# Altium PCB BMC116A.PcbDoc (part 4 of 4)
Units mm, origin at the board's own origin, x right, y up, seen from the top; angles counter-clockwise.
Board outline 154.94 x 104.14 mm, 6 copper layers (Top Layer, Signal Layer 1, Signal Layer 2, Signal Layer 3, Signal Layer 4, Bottom Layer), stack 1.56 mm thick; 252 components, 114 nets, 652 pads, 2530 vias.
Unrouted connection lines stored in the file: 13.
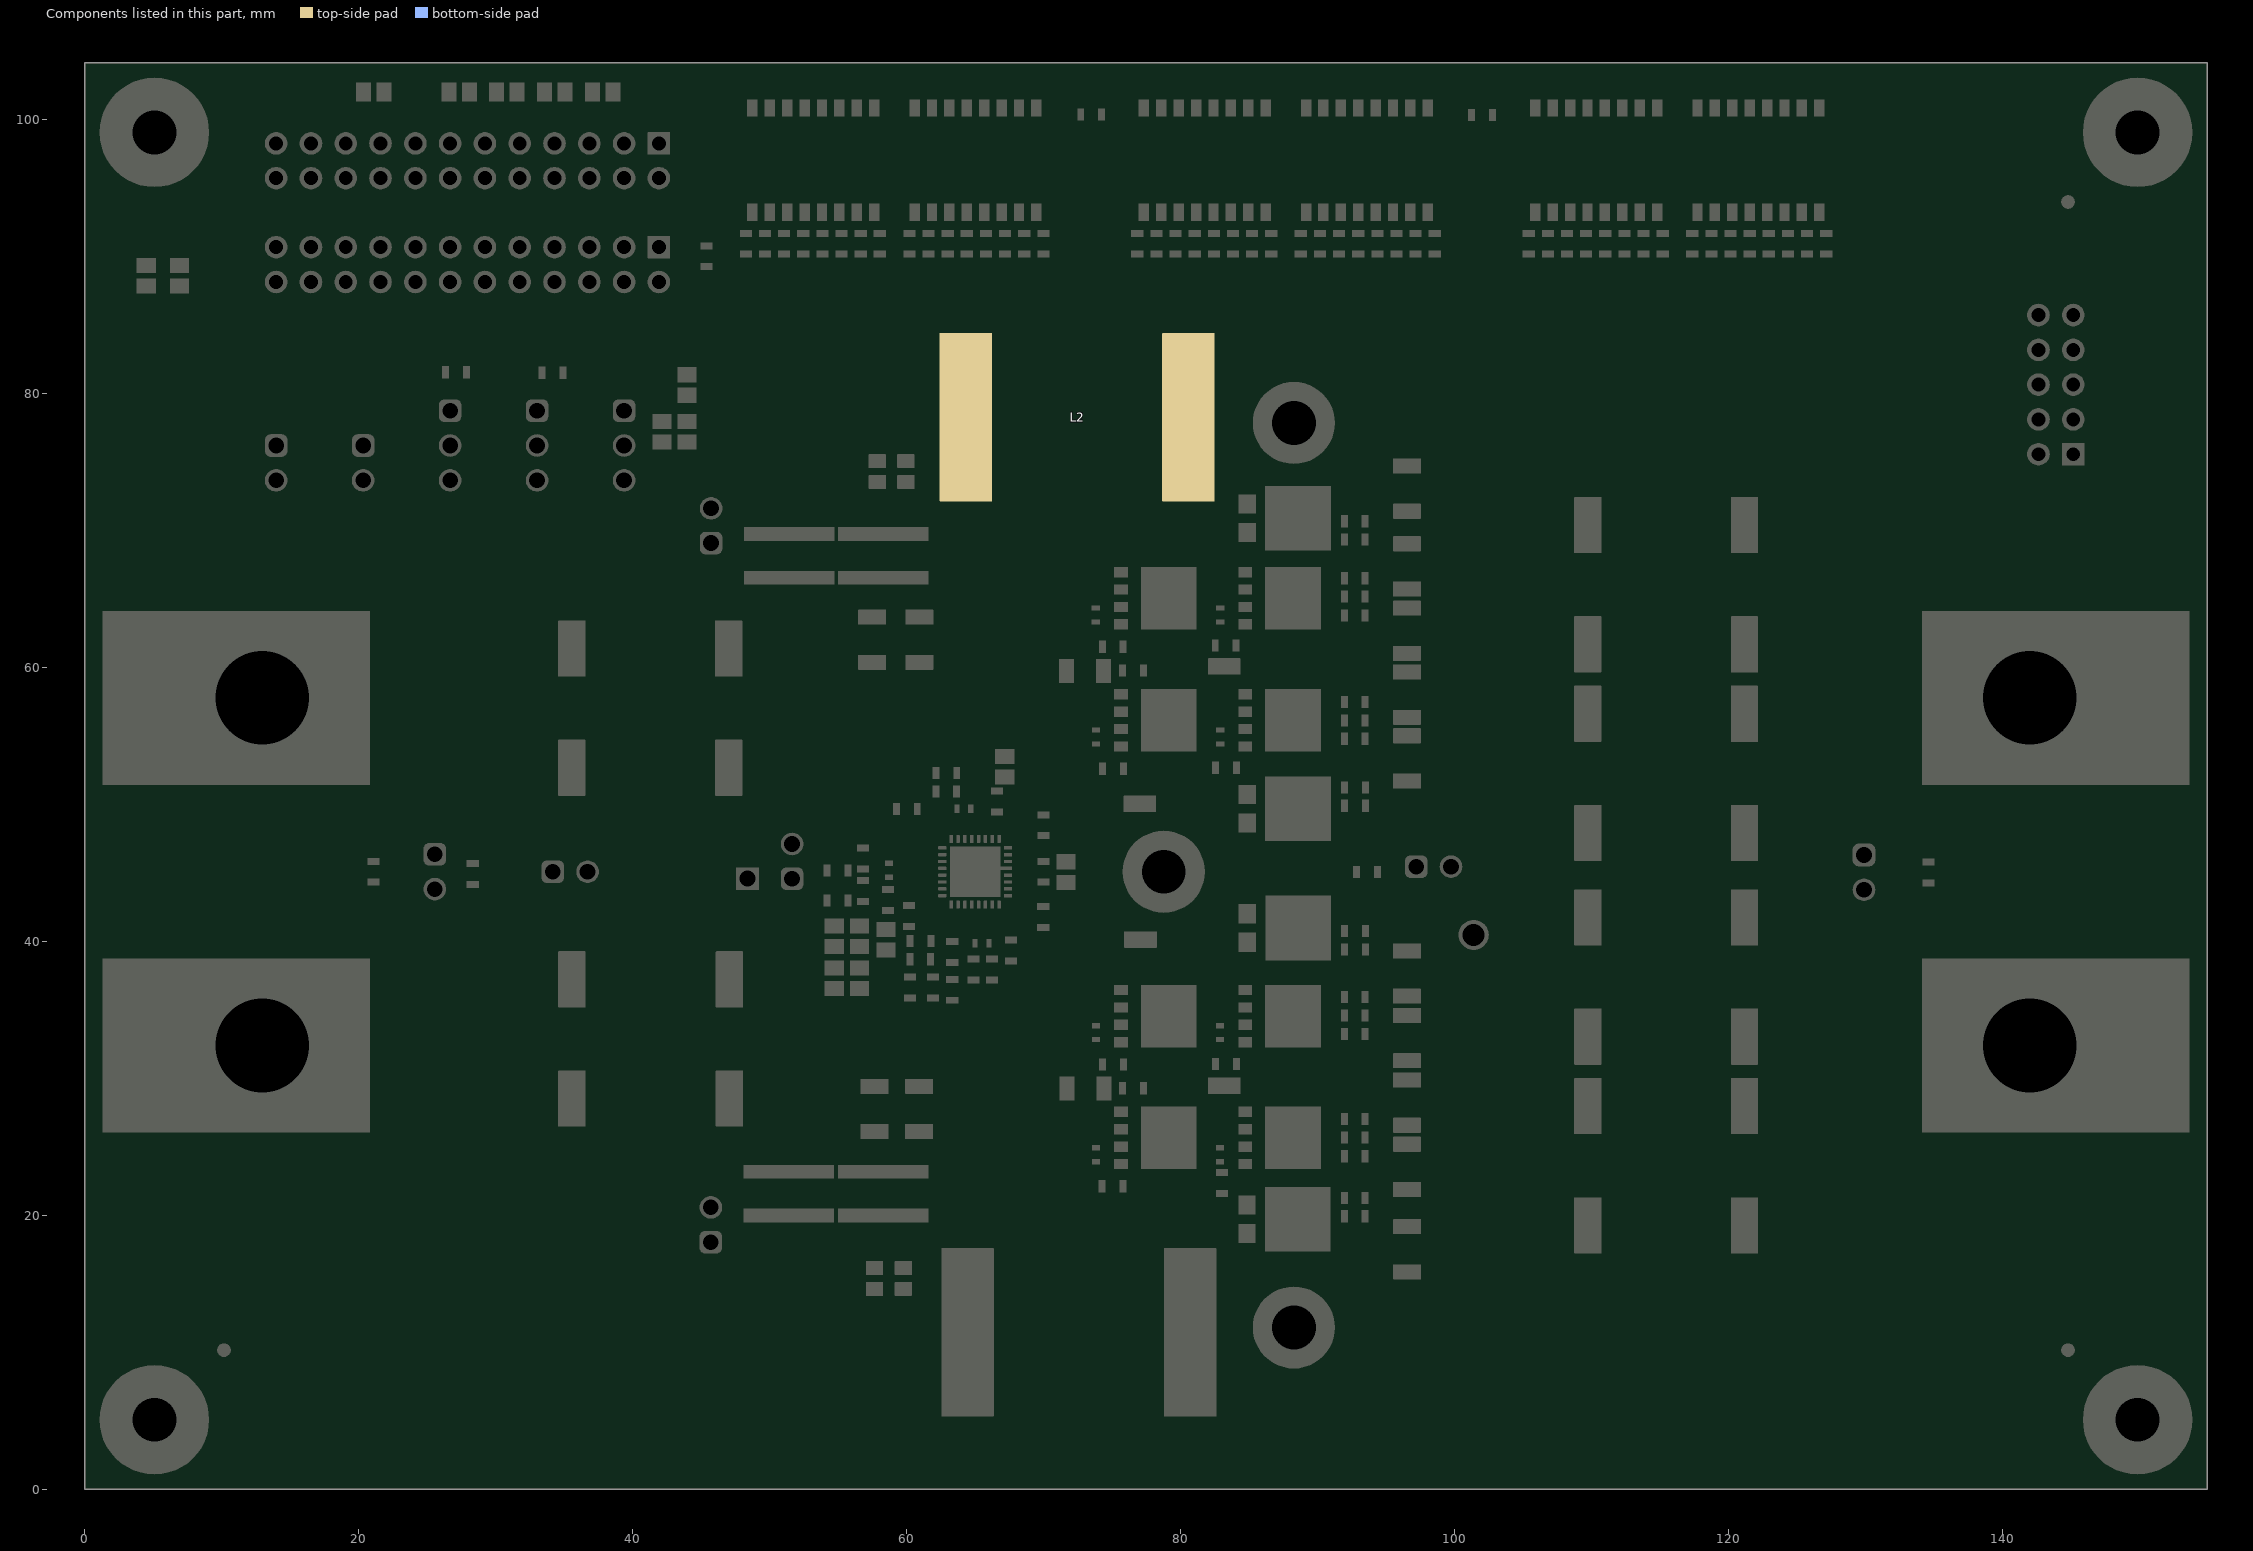
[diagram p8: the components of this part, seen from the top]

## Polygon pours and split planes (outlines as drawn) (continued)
AGND on Top Layer "TOP_LAYER_AGND_P106" (solid, pour order 106): 54.666,51.983 50.361,47.677 50.361,38.929 54.382,34.907 66.117,34.907 68.147,36.938 68.147,40.746 67.196,41.697 67.196,47.527 67.846,48.177 67.846,54.07 66.872,55.045 57.729,55.045
VIN on Top Layer "TOP_LAYER_VIN_P107" (solid, pour order 107): 30.48,22.595 31.197,21.878 61.963,21.878 61.963,27.444 61.54,27.867 62.851,27.924 50.892,27.919 47.741,31.07 31.197,31.07 30.48,30.353
VIN on Top Layer "TOP_LAYER_VIN_P108" (solid, pour order 108): 30.503,59.468 30.503,67.206 31.149,67.852 61.987,67.852 61.987,62.079 61.727,61.819 50.721,61.807 47.715,58.801 31.17,58.801
SW2 on Top Layer "TOP_LAYER_SW2_P109" (solid, pour order 109): 85.528,47.938 85.394,47.804 82.005,47.804 77.02,52.789 77.02,72.111 74.704,74.949 74.704,80.783 78.416,84.494 82.989,84.494 83.386,84.098 83.386,74.558 84.623,73.356 85.528,73.356 85.528,68.383
VOUT on Top Layer "Bottom Layer-VOUT" (solid, pour order 110): 130.5,45.095 129.307,44.926 128.679,44.648 126.251,42.219 124.968,38.73 124.968,27.161 122.353,23.823 118.788,22.225 105.001,22.225 100.063,17.287 86.106,17.286 86.117,44.196 86.117,46.568 86.106,46.568 86.106,73.356 99.971,73.356 101.243,72.084 106.017,67.31 118.237,67.31 154.94,67.31 154.94,45.095
VIN on Top Layer "TOP_LAYER_VIN_P130" (solid, remove dead copper, pour order 130): 23.497,66.112 23.497,49.085 22.859,48.448 0,48.448 0,66.733 22.876,66.733
GND on Top Layer "TOP_LAYER_AGND_P479" (solid, pour order 131): -0.666,104.208 154.274,104.208 154.274,0.068 -0.666,0.068
GND on Top Layer "TOP_LAYER_GND_P132" (solid, pour order 132): 92.892,32.786 93.052,32.626 97.51,32.626 97.962,33.078 97.962,35.656 97.092,36.525 93.088,36.525 92.892,36.329
GND on Top Layer "TOP_LAYER_GND_P008" (solid, pour order 8): 92.892,54.306 93.065,54.132 97.79,54.132 97.962,54.304 97.962,57.12 97.037,58.045 93.088,58.045 92.892,57.848
GND on Bottom Layer "BOTTOM_LAYER_GND_P066" (solid, pour order 66): 56.96,30.206 56.96,28.69 57.166,28.484 62.038,28.484 62.313,28.759 62.313,30.041 61.966,30.387 57.185,30.387
GND on Bottom Layer "BOTTOM_LAYER_GND_P081" (solid, pour order 81): 57.017,59.556 57.017,61.072 57.223,61.278 62.095,61.278 62.37,61.003 62.37,59.721 62.024,59.375 57.243,59.375
VOUT on Bottom Layer "Bottom Layer-VOUT 1" (solid, pour order 117): 86.454,47.602 86.646,47.41 90.399,47.41 90.599,47.611 90.599,58.906 90.417,59.089 86.633,59.089 86.454,58.866
VOUT on Bottom Layer "Bottom Layer-VOUT 2" (solid, pour order 116): 86.445,31.796 86.61,31.631 90.42,31.631 90.611,31.823 90.611,43.062 90.409,43.265 86.656,43.265 86.445,43.054
VOUT on Bottom Layer "Bottom Layer-VOUT 3" (solid, pour order 112): 90.402,17.469 90.573,17.681 90.573,28.453 90.417,28.609 86.633,28.609 86.445,28.376 86.445,17.653 86.63,17.469
VOUT on Bottom Layer "Bottom Layer-VOUT 4" (solid, pour order 91): 86.471,62.25 86.61,62.111 90.42,62.111 90.573,62.264 90.573,72.991 90.395,73.17 86.642,73.17 86.471,72.999
SW2 on Bottom Layer "BOTTOM_LAYER_SW2_P121" (solid, remove dead copper, pour order 121): 77.304,68.646 81.087,68.646 81.241,68.492 81.241,61.622 81.06,61.441 77.305,61.441 77.124,61.622 77.124,68.423
SW2 on Bottom Layer "BOTTOM_LAYER_SW2_P120" (solid, pour order 120): 77.303,59.748 81.086,59.748 81.24,59.594 81.24,52.723 81.059,52.543 77.304,52.543 77.124,52.723 77.124,59.525
SW1 on Bottom Layer "BOTTOM_LAYER_SW1_P119" (solid, pour order 119): 77.303,29.268 81.086,29.268 81.24,29.114 81.24,22.244 81.059,22.063 77.304,22.063 77.124,22.243 77.124,29.045
SW1 on Bottom Layer "BOTTOM_LAYER_SW1_P118" (solid, pour order 118): 77.304,38.166 81.087,38.166 81.241,38.012 81.241,31.142 81.06,30.961 77.305,30.961 77.124,31.142 77.124,37.943
AGND on Bottom Layer "Bottom Layer-AGND" (solid, remove dead copper, pour order 126): 35.434,44.314 49.332,30.314 49.332,24.198 63.06,24.198 68.022,29.16 68.022,40.637 67.317,41.343 66.51,41.343 65.75,42.103 65.75,43.248 66.86,44.358 66.86,45.788 65.696,46.952 65.696,47.871 68.022,50.197 68.089,76.912 49.332,95.669 49.332,95.668 41.482,103.518 0.647,103.518 0.647,68.286 41.934,68.314 44.32,65.928 49.332,65.928 49.332,59.666 35.434,45.768
GND on Bottom Layer "BOTTOM_LAYER_GND_P125" (solid, remove dead copper, pour order 125): 59.866,61.287 62.023,61.287 62.37,60.939 62.37,59.721 62.032,59.383 59.863,59.383 59.532,59.714 59.532,60.953
GND on Bottom Layer "BOTTOM_LAYER_GND_P124" (solid, remove dead copper, pour order 124): 57.225,61.287 58.721,61.287 59.068,60.939 59.068,59.721 58.73,59.383 57.203,59.383 57.017,59.569 57.017,61.079
GND on Bottom Layer "BOTTOM_LAYER_GND_P123" (solid, remove dead copper, pour order 123): 57.2,28.459 58.695,28.459 59.043,28.806 59.043,30.024 58.704,30.363 57.178,30.363 56.992,30.177 56.992,28.666
GND on Bottom Layer "BOTTOM_LAYER_GND_P122" (solid, remove dead copper, pour order 122): 59.808,28.475 61.965,28.475 62.313,28.823 62.313,30.041 61.974,30.379 59.805,30.379 59.474,30.048 59.474,28.809
VOUT on Bottom Layer "BOTTOM_LAYER_VOUT_P127" (solid, remove dead copper, pour order 127): 131.217,49.293 131.217,66.32 131.935,67.038 154.94,67.038 154.94,48.673 131.838,48.673
GND on Bottom Layer "BOTTOM_LAYER_GND_P128" (solid, remove dead copper, pour order 128): 23.723,40.877 23.723,23.85 23.005,23.132 0,23.132 0,41.497 23.102,41.497
VIN on Bottom Layer "Bottom Layer-VIN" (solid, remove dead copper, pour order 129): 48.768,24.211 44.01,24.211 41.588,21.789 0,21.789 0,67.775 41.828,67.775 44.017,65.586 48.768,65.586
GND on Bottom Layer "TOP_LAYER_AGND_P479" (solid, pour order 134): 0,104.14 154.94,104.14 154.94,0 0,0
VOUT on Bottom Layer "BOTTOM_LAYER_VOUT_P133" (solid, remove dead copper, pour order 133): 131.217,49.293 131.217,66.32 131.855,66.958 154.94,66.958 154.94,48.673 131.838,48.673
GND on Signal Layer 2 "Signal Layer 2-GND" (solid, remove dead copper, pour order 29): 74.439,21.512 75.252,22.324 75.252,66.938 74.371,67.818 69.175,67.818 68.58,67.223 68.58,50.014 66.336,47.77 66.336,46.991 67.337,45.99 67.34,44.083 66.287,43.029 66.287,42.241 66.776,41.752 67.613,41.752 68.58,40.785 68.58,21.917 68.986,21.512
AGND on Signal Layer 2 "TOP_LAYER_AGND_P479" (solid, pour order 51): 0,104.14 154.94,104.14 154.94,0 0,0
GND on Signal Layer 3 "Signal Layer 3-GND" (solid, remove dead copper, pour order 70): 85.695,28.878 85.695,31.323 85.695,59.358 85.695,61.803 85.695,65.588 82.65,68.632 70.04,68.632 68.58,67.172 68.58,50.014 66.336,47.77 66.336,47.005 67.345,45.996 67.348,44.103 66.287,43.041 66.287,42.257 66.8,41.743 67.585,41.743 68.58,40.748 68.58,21.928 69.004,21.503 83.796,21.503 85.695,23.402
AGND on Signal Layer 3 "TOP_LAYER_AGND_P479" (solid, pour order 72): 0,104.14 154.94,104.14 154.94,0 0,0
GND on Signal Layer 4 "Signal Layer 4-GND" (solid, remove dead copper, pour order 47): 85.695,23.402 85.695,65.588 82.651,68.631 70.039,68.631 68.58,67.172 68.58,49.982 66.26,47.662 66.26,47.134 67.356,46.038 67.359,44.114 66.287,43.041 66.287,42.257 66.797,41.747 67.489,41.747 68.58,40.656 68.58,21.928 69.426,21.082 83.375,21.082
AGND on Signal Layer 4 "TOP_LAYER_AGND_P479" (solid, pour order 50): 0,104.14 154.94,104.14 154.94,0 0,0
no net on Top Solder "TOP_LAYER_NONET_P111" (solid): 71.602,10.338 70.408,10.338 70.408,13.696 71.602,13.696
no net on Top Solder "TOP_LAYER_NONET_P111" (solid): 71.472,79.391 70.278,79.391 70.278,76.033 71.472,76.033
no net on Top Solder "TOP_LAYER_NONET_P111" (solid): 70.179,8.919 66.639,8.919 66.639,14.765 70.179,14.765
no net on Top Solder "TOP_LAYER_NONET_P111" (solid): 74.96,8.919 78.5,8.919 78.5,14.765 74.96,14.765
no net on Top Solder "TOP_LAYER_NONET_P111" (solid): 74.83,80.81 78.37,80.81 78.37,74.964 74.83,74.964
L2 on Top Solder "TOP_LAYER_NONET_P111" (solid, pour order 111): 70.049,80.81 66.51,80.81 66.51,74.964 70.049,74.964
GND on Signal Layer 1 "TOP_LAYER_AGND_P479" (solid, pour order 25): 0,104.14 154.94,104.14 154.94,0 0,0
VOUT on Bottom Solder (solid, pour order 32): 86.471,62.25 86.61,62.111 90.42,62.111 90.573,62.264 90.573,72.991 90.395,73.17 86.642,73.17 86.471,72.999
VOUT on Bottom Solder (solid, pour order 33): 90.402,17.469 90.573,17.681 90.573,28.453 90.417,28.609 86.633,28.609 86.445,28.376 86.445,17.653 86.63,17.469
VOUT on Bottom Solder (solid, pour order 34): 86.445,31.796 86.61,31.631 90.42,31.631 90.611,31.823 90.611,43.062 90.409,43.265 86.656,43.265 86.445,43.054
VOUT on Bottom Solder (solid, pour order 35): 86.454,47.602 86.646,47.41 90.399,47.41 90.599,47.611 90.599,58.906 90.417,59.089 86.633,59.089 86.454,58.866
SW2 on Bottom Solder "BOTTOM_LAYER_SW2_P035" (solid, pour order 115): 77.304,68.646 81.087,68.646 81.241,68.492 81.241,61.622 81.06,61.441 77.305,61.441 77.124,61.622 77.124,68.423
SW1 on Bottom Solder "BOTTOM_LAYER_SW1_P033" (solid, pour order 113): 77.303,29.268 81.086,29.268 81.24,29.114 81.24,22.244 81.059,22.063 77.304,22.063 77.124,22.243 77.124,29.045
SW1 on Bottom Solder "BOTTOM_LAYER_SW1_P032" (solid, pour order 53): 77.304,38.166 81.087,38.166 81.241,38.012 81.241,31.142 81.06,30.961 77.305,30.961 77.124,31.142 77.124,37.943
SW2 on Bottom Solder "BOTTOM_LAYER_SW2_P034" (solid, pour order 114): 77.303,59.748 81.086,59.748 81.24,59.594 81.24,52.723 81.059,52.543 77.304,52.543 77.124,52.723 77.124,59.525

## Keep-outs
Keep-Out Layer:
  text ".Layer_Name" at 14.656,-21.806 h1.52

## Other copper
Top Layer:
  pour cut-out: 44.614,20.547 ccw(c45.721,20.547) 45.721,19.44 ccw(c45.721,20.547) 46.827,20.547 ccw(c45.721,20.547) 45.721,21.653 ccw(c45.721,20.547)
  pour cut-out: 24.424,43.82 ccw(c25.53,43.82) 25.53,42.713 ccw(c25.53,43.82) 26.637,43.82 ccw(c25.53,43.82) 25.53,44.926 ccw(c25.53,43.82)
  pour cut-out: 128.779,43.759 ccw(c129.885,43.759) 129.885,42.653 ccw(c129.885,43.759) 130.992,43.759 ccw(c129.885,43.759) 129.885,44.866 ccw(c129.885,43.759)
  pour cut-out: 24.424,46.36 ccw(c25.53,46.36) 25.53,45.253 ccw(c25.53,46.36) 26.637,46.36 ccw(c25.53,46.36) 25.53,47.466 ccw(c25.53,46.36)
  pour cut-out: 128.758,46.426 ccw(c129.864,46.426) 129.864,45.319 ccw(c129.864,46.426) 130.971,46.426 ccw(c129.864,46.426) 129.864,47.532 ccw(c129.864,46.426)
  pour cut-out: 66.935,39.57 66.935,39.003 66.612,39.003 66.612,39.57
  pour cut-out: 68.649,39.086 68.649,37.745 68.327,37.745 68.327,39.086
  pour cut-out: 66.761,48.907 66.761,47.895 66.557,47.895 66.557,48.907
  pour cut-out: 27.619,46.196 27.619,43.628 29.029,43.628 29.029,46.196
  pour cut-out: 66.469,72.076 71.514,76.007 71.514,79.394 66.376,84.532 66.376,85.01 78.554,85.01 78.544,84.645 74.738,80.839 74.738,74.909 77.018,72.111 77.018,71.589 66.469,71.589
  pour cut-out: 61.982,71.589 61.982,74.549 62.49,74.549 62.49,71.589
  pour cut-out: 66.574,17.673 71.677,13.696 71.677,10.369 66.25,4.942 66.25,4.719 78.684,4.719 78.674,5.085 74.868,8.891 74.868,14.82 76.984,17.417 76.984,18.14 66.599,18.14 66.574,18.115
  pour cut-out: 63.148,52.661 63.148,53.691 63.765,53.691 63.765,52.661
  pour cut-out: 46.55,21.77 46.55,18.741 48.042,18.741 48.042,21.77
  pour cut-out: 67.841,48.692 66.557,48.692 66.557,48.896 67.841,48.896
  pour cut-out: 65.338,38.617 65.338,39.239 65.785,39.239 65.785,38.617
  pour cut-out: 61.982,67.345 61.982,69.529 62.49,69.529 62.49,67.345
  pour cut-out: 61.958,20.33 61.958,22.514 62.466,22.514 62.466,20.33
  pour cut-out: 61.957,17.364 61.957,15.18 62.465,15.18 62.465,17.364
  pour cut-out: 54.257,74.905 55.781,74.905 55.781,74.397 54.257,74.397
  pour cut-out: 61.578,42.218 61.578,43.009 62.478,43.009 62.478,42.218
  pour cut-out: 134.102,42.674 129.885,42.674 129.885,44.679 134.102,44.679
  pour cut-out: 134.121,45.44 129.882,45.44 129.882,47.532 134.121,47.532
  pour cut-out: 128.779,43.841 128.779,46.383 134.102,46.383 134.102,43.841
  pour cut-out: 43.079,21.872 56.974,21.872 56.974,21.364 43.079,21.364
  pour cut-out: 85.598,31.831 85.598,28.194 86.106,28.194 86.106,31.831
  pour cut-out: 85.582,62.461 85.582,58.824 86.09,58.824 86.09,62.461
  pour cut-out: 46.568,67.891 46.568,70.92 48.118,70.92 48.118,67.891
  pour cut-out: 67.841,48.703 67.841,54.807 68.411,54.237 68.428,50.322 68.432,49.294
  pour cut-out: 54.077,14.799 55.601,14.799 55.601,15.307 54.077,15.307
  pour cut-out: 66.211,39.57 68.613,39.57 68.613,41.972
  pour cut-out: 43.249,68.369 57.051,68.369 57.051,67.861 43.249,67.861
  text ".Layer_Name" at 14.656,-21.806 h1.52
Signal Layer 1:
  pour cut-out: 24.424,43.818 ccw(c25.531,43.818) 25.531,42.711 ccw(c25.531,43.818) 26.637,43.818 ccw(c25.531,43.818) 25.531,44.924 ccw(c25.531,43.818)
  pour cut-out: 24.427,46.358 ccw(c25.533,46.358) 25.533,45.251 ccw(c25.533,46.358) 26.64,46.358 ccw(c25.533,46.358) 25.533,47.464 ccw(c25.533,46.358)
  pour cut-out: 128.782,43.772 ccw(c129.889,43.772) 129.889,42.665 ccw(c129.889,43.772) 130.995,43.772 ccw(c129.889,43.772) 129.889,44.878 ccw(c129.889,43.772)
  pour cut-out: 128.782,46.312 ccw(c129.889,46.312) 129.889,45.205 ccw(c129.889,46.312) 130.995,46.312 ccw(c129.889,46.312) 129.889,47.418 ccw(c129.889,46.312)
  pour cut-out: 27.619,46.196 27.619,43.628 29.029,43.628 29.029,46.196
  pour cut-out: 69.293,46.307 69.917,46.307 69.917,43.837 69.293,43.837
  text ".Layer_Name" at 14.656,-21.806 h1.52
Signal Layer 2:
  pour cut-out: 24.467,45.943 24.464,45.939 24.464,43.815 24.965,43.815 24.965,45.946
  pour cut-out: 84.151,45.544 75.77,45.544 75.77,44.574 75.77,39.472 84.151,44.648
  text ".Layer_Name" at 14.656,-21.806 h1.52
Signal Layer 3:
  pour cut-out: 65.987,47.076 66.296,47.384 68.219,45.461 70.454,45.461 71.089,44.826 70.56,44.298 70.213,44.644 67.807,44.644 67.024,45.427 67.024,45.697
  pour cut-out: 76.586,69.152 81.793,69.152 81.793,68.644 76.586,68.644
  text ".Layer_Name" at 14.656,-21.806 h1.52
Signal Layer 4:
  pour cut-out: 76.483,69.148 81.69,69.148 81.69,68.64 76.483,68.64
  text ".Layer_Name" at 14.656,-21.806 h1.52
Bottom Layer:
  pour cut-out: 128.771,43.79 ccw(c129.878,43.79) 129.878,42.683 ccw(c129.878,43.79) 130.985,43.79 ccw(c129.878,43.79) 129.878,44.896 ccw(c129.878,43.79)
  pour cut-out: 24.427,46.358 ccw(c25.533,46.358) 25.533,45.251 ccw(c25.533,46.358) 26.64,46.358 ccw(c25.533,46.358) 25.533,47.464 ccw(c25.533,46.358)
  pour cut-out: 128.774,46.314 ccw(c129.881,46.314) 129.881,45.207 ccw(c129.881,46.314) 130.988,46.314 ccw(c129.881,46.314) 129.881,47.42 ccw(c129.881,46.314)
  pour cut-out: 24.427,43.818 ccw(c25.533,43.818) 25.533,42.711 ccw(c25.533,43.818) 26.64,43.818 ccw(c25.533,43.818) 25.533,44.924 ccw(c25.533,43.818)
  pour cut-out: 26.64,47.006 26.188,47.457 24.842,47.457 24.434,47.049 24.434,45.704 24.89,45.249 26.179,45.249 26.64,45.709
  pour cut-out: 27.746,46.058 27.746,44.325 28.885,44.325 28.885,46.058
  text ".Layer_Name" at 14.656,-21.806 h1.52

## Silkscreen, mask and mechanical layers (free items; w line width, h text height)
Top Overlay:
  lines w0.254: 1.554,46.193 1.535,42.425 17.503,42.425 ; 1.57,46.242 17.538,46.242 ; 17.52,42.459 17.538,46.227 ; 51.636,42.627 51.636,43.326 ; 51.641,48.334 51.641,49.033 ; 135.541,46.747 135.523,42.979 153.523,42.979 ; 135.557,46.795 153.557,46.795 ; 153.539,43.013 153.558,46.781
  text "CFG0" at 57.658,102.235 h0.76
  text "CFG1" at 86.233,102.235 h0.76
  text "CFG2" at 114.808,102.235 h0.76
  text "ATRK" at 25.47,100.119 h0.76
  text "PGOOD" at 29.011,100.119 h0.76
  text "SYNCIN" at 41.5,100.119 h0.76
  text "UVLO" at 36.921,100.1 h0.76
  text "EN2" at 33.513,100.066 h0.76
  text "MODE" at 19.876,100.009 h0.76
  text "SECONDARY" at 11.639,93.708 h0.76 r90
  text "SYNCOUT" at 41.298,92.81 h0.76
  text "PULL-UP" at 3.179,92.036 h0.76
  text "RESISTORS" at 2.485,90.678 h0.76
  text "PRIMARY" at 11.639,87.037 h0.76 r90
  text "SDA" at 137.017,85.309 h0.76
  text "SCL" at 149.013,85.309 h0.76
  text "SS" at 27.028,85.106 h0.76 r90
  text "SDA" at 4.932,84.458 h0.76 r90
  text "SCL" at 7.128,84.458 h0.76 r90
  text "SDA" at 14.254,84.344 h0.76 r90
  text "SCL" at 16.809,84.344 h0.76 r90
  text "EN2" at 34.692,84.344 h0.76 r90
  text "MODE" at 21.918,83.583 h0.76 r90
  text "COMP" at 24.473,83.583 h0.76 r90
  text "ATRK" at 29.582,83.583 h0.76 r90
  text "SYNC" at 42.25,83.583 h0.76 r90
  text "PGOOD" at 32.137,82.821 h0.76 r90
  text "UVLO/EN" at 37.246,81.297 h0.76 r90
  text "ILIM/IMON" at 19.363,80.155 h0.76 r90
  text "AGND" at 136.588,79.982 h0.76
  text "FPWM" at 22.059,78.983 h0.76
  text "0.34*" at 35.054,78.877 h1.65
  text "VCC" at 29.432,78.209 h0.76
  text "VCC" at 23.069,77.836 h0.76
  text "BIAS" at 35.037,77.836 h0.76
  text "PHASE 2" at 100.757,77.343 h1.02
  text "ATRK" at 9.55,75.567 h0.76
  text "DLY" at 16.697,75.567 h0.76
  text "MODE" at 22.307,75.567 h0.76
  text "EN2" at 29.432,75.567 h0.76
  text "UVLO" at 34.91,75.567 h0.76
  text "AGND" at 22.352,73.615 h0.76
  text "AGND" at 9.55,73.232 h0.76
  text "AGND" at 15.936,73.232 h0.76
  text "AGND" at 28.671,73.232 h0.76
  text "BIAS" at 35.037,73.232 h0.76
  text "DEM" at 23.057,72.434 h0.76
  text "RS2" at 42.097,71.104 h0.76
  text "VIN" at 42.097,68.692 h0.76
  text "VOUT" at 131,57 h0.76 r90
  text "VIN" at 24.748,56.534 h0.76 r90
  text "ATRK" at 50.496,50.483 h0.76
  text "EXTERNAL" at 48.965,49.435 h0.76
  text "BODE" at 99.978,48.392 h0.76
  text "VOUT_7" at 91.5,45.992 h0.76
  text "VIN" at 22.934,45.851 h0.76 r90
  text "S+" at 23.975,45.847 h0.76 r90
  text "VOUT" at 101.302,45.749 h0.76
  text "VOUT" at 133.36,45.506 h0.76 r90
  text "S+" at 132.11,45.494 h0.76 r90
  text "12.5A MAX" at 136.009,43.862 h2.03
  text "AGND" at 43.7,43.662 h0.76
  text "26A MAX" at 2.595,43.284 h2.03
  text "S-" at 23.975,43.205 h0.76 r90
  text "S-" at 132.144,42.653 h0.76 r90
  text "VIN" at 32.467,42.573 h0.76
  text "BIAS" at 36.539,42.573 h0.76
  text "GND" at 22.866,42.453 h0.76 r90
  text "GND" at 133.341,41.835 h0.76 r90
  text "ATRK/DTRK" at 44.534,41.752 h0.76
  text "AGND" at 99.97,37.539 h0.76
  text "GND" at 131.069,31.6 h0.76 r90
  text "45V" at 54.471,31.234 h0.76 r90
  text "24V" at 57.167,31.199 h0.76 r90
  text "GND" at 24.49,31.16 h0.76 r90
  text "ATRK" at 55.808,29.765 h0.76 r90
  text "VIN" at 42.097,20.134 h0.76
  text "RS1" at 42.097,17.632 h0.76
  text "'.PRJ_Title'" at 15.001,13.962 h1.52
  text ".PRJ_Number" at 14.95,11.828 h1.02
  text "PHASE 1" at 100.757,11.303 h1.02
  text "REV. .PCB_Rev" at 14.95,9.75 h1.02
  text ".Layer_Name" at 14.656,-21.806 h1.52
Bottom Overlay:
  text ".Layer_Name" at 14.656,-21.806 h1.52
Top Paste:
  text ".Layer_Name" at 14.656,-21.806 h1.52
Bottom Paste:
  text ".Layer_Name" at 14.656,-21.806 h1.52
Top Solder:
  text ".Layer_Name" at 14.656,-21.806 h1.52
  text ".Layer_Name" at 14.656,-21.806 h1.52
Bottom Solder:
  text ".Layer_Name" at 14.656,-21.806 h1.52
Drill Guide:
  text ".Layer_Name" at 14.656,-21.806 h1.52
M1 Board Outline:
  the board outline again, w0.254
  text ".Layer_Name" at 14.656,-21.806 h1.52
M2 Board Dimensions:
  rectangle: 0,-6.985 3.175,-3.81
  rectangle: 3.175,-10.16 12.7,-6.985
  lines w0.178: 0,-6.985 25.4,-6.985 ; 3.175,-10.16 3.175,-3.81 ; 6.35,-10.16 6.35,-3.81 ; 12.7,-10.16 12.7,-3.81 ; 19.05,-10.16 19.05,-3.81 ; 0,-10.16 25.4,-10.16 25.4,-3.81 0,-3.81 0,-10.16
  text ".Layer_Name" at 14.656,-21.806 h1.52
M3 3D STEP Top:
  text ".Layer_Name" at 14.656,-21.806 h1.52
M4 3D STEP Bottom:
  text ".Layer_Name" at 14.656,-21.806 h1.52
M5 Assembly Top:
  lines w0.254: -7.417,-23.626 160.223,-23.626 ; -7.417,-18.462 160.274,-18.462 ; -7.417,-13.297 -7.417,-28.791 94.31,-28.791 160.274,-28.791 160.274,-13.297 -7.404,-13.297 -7.404,-28.791 32.614,-28.791 ; 55.194,-28.791 55.194,-13.297 ; 87.376,-18.462 87.376,-13.297 ; 108.712,-18.462 108.712,-13.297 ; 124.511,-28.956 124.511,-23.804
  text "COMPONENTS MARKED 'DNP' SHOULD NOT BE POPULATED." at 29.299,-8.09 h1.52
  text "ASSEMBLY VARIANT:" at 29.286,-11.024 h1.52
  text ".VariantName" at 55.601,-11.024 h1.52
  text "PCB VIEWED FROM TOP SIDE" at -5.804,-16.654 h1.52
  text "BOARD #:" at 57.099,-16.654 h1.52
  text ".PRJ_Number" at 70.955,-16.654 h1.52
  text "REV:" at 92.405,-16.654 h1.52
  text ".PCB_Rev" at 99.809,-16.654 h1.52
  text "SVN REV:" at 113.69,-16.654 h1.52
  text ".VersionControl_RevNumber" at 126.543,-16.654 h1.52
  text "TID #:" at 57.099,-21.819 h1.52
  text ".TID" at 70.955,-21.819 h1.52
  text "PLOT NAME =" at -5.804,-27.034 h1.52
  text ".plot_File_Name" at 14.656,-27.034 h1.52
  text "GENERATED    :" at 57.15,-27.034 h1.52
  text ".Print_Date" at 79.235,-27.034 h1.52
  text ".Print_Time" at 97.752,-27.034 h1.52
  text "TEXAS INSTRUMENTS" at 129.87,-27.034 h1.52
M6 Assembly Bottom:
  lines w0.254: -7.429,-18.474 160.261,-18.474 ; -7.379,-23.639 160.261,-23.639 ; 28.334,-28.969 28.334,-23.817 ; 44.133,-18.474 44.133,-13.31 ; 65.468,-18.474 65.468,-13.31 ; 97.65,-28.804 97.65,-13.31 ; 120.231,-28.804 160.249,-28.804 160.249,-13.31 -7.429,-13.31 -7.429,-28.804 58.534,-28.804 160.261,-28.804 160.261,-13.31
  text "COMPONENTS MARKED 'DNP' SHOULD NOT BE POPULATED." at 154.991,-8.077 h1.52
  text ".VariantName" at 128.473,-11.024 h1.52
  text "ASSEMBLY VARIANT:" at 154.864,-11.024 h1.52
  text ".VersionControl_RevNumber" at 26.302,-16.667 h1.52
  text "SVN REV:" at 39.154,-16.667 h1.52
  text ".PCB_Rev" at 53.035,-16.667 h1.52
  text "REV:" at 60.439,-16.667 h1.52
  text ".PRJ_Number" at 81.89,-16.667 h1.52
  text "BOARD #:" at 95.745,-16.667 h1.52
  text "PCB VIEWED FROM BOTTOM SIDE" at 158.648,-16.667 h1.52
  text ".TID" at 81.89,-21.831 h1.52
  text "TID #:" at 95.745,-21.831 h1.52
  text "TEXAS INSTRUMENTS" at 22.974,-27.047 h1.52
  text ".Print_Time" at 55.093,-27.047 h1.52
  text ".Print_Date" at 73.609,-27.047 h1.52
  text "GENERATED    :" at 95.694,-27.047 h1.52
  text ".plot_File_Name" at 138.189,-27.047 h1.52
  text "PLOT NAME =" at 158.648,-27.047 h1.52
M9 Title Sheet:
  drawing of 57 lines, arcs and shapes, not listed
  text "1" at 18.792,204.127 h1.78
  text "2" at 82.182,204.127 h1.78
  text "3" at 145.411,204.127 h1.78
  text "4" at 209.08,204.127 h1.78
  text "5" at 272.555,204.127 h1.78
  text "6" at 336.182,204.127 h1.78
  text "A" at -10.579,175.095 h1.78
  text "A" at 365.341,175.095 h1.78
  text "B" at -10.579,114.643 h1.78
  text "B" at 365.341,114.643 h1.78
  text "C" at -10.579,54.318 h1.78
  text "C" at 365.341,54.318 h1.78
  text "PROJECT TITLE:" at 288.125,7.048 h1.14
  text ".PRJ_Title" at 289.395,3.662 h1.78
  text "DESIGNED FOR:" at 288.125,-0.597 h1.14
  text ".PRJ_Customer" at 289.395,-4.153 h1.78
  text "D" at -10.579,-5.88 h1.78
  text "D" at 365.341,-5.88 h1.78
  text "FILE NAME:" at 288.125,-8.217 h1.14
  text ".PCB_File_Name_No_Path" at 289.395,-11.265 h1.78
  text "Texas Instruments (TI) and/or its licensors do not warrant the accuracy or completeness of this specification" at 161.9,-15.376 h1.14
  text "ENGINEER:" at 288.125,-15.583 h1.14
  text "LAYOUT BY:" at 326.352,-15.583 h1.14
  text "or any information contained therein. TI and/or its licensors do not warrant that this design will meet" at 160.757,-18.237 h1.14
  text ".PRJ_Engineer" at 289.395,-19.52 h1.78
  text ".PCB_Layout" at 327.635,-19.52 h1.78
  text "the specifications, will be suitable for your application or fit for any particular purpose, or will operate in" at 160.757,-21.099 h1.14
  text ".Layer_Name" at 14.656,-21.806 h1.52
  text "ALTIUM DESIGNER VERSION:" at 326.352,-23.457 h1.14
  text "an implementation. TI and/or its licensors do not warrant that the design is production worthy. You should" at 160.757,-23.961 h1.14
  text "completely validate and test your design implementation to confirm the system functionality for your application." at 161.9,-26.822 h1.14
  text ".print_Scale" at 289.395,-26.843 h1.78
  text ".Application_BuildNumber" at 327.635,-26.843 h1.78
  text "1" at 18.792,-32.093 h1.78
  text "2" at 82.182,-32.093 h1.78
  text "3" at 145.411,-32.093 h1.78
  text "4" at 209.08,-32.093 h1.78
  text "5" at 272.555,-32.093 h1.78
  text "6" at 336.182,-32.093 h1.78
M10 Fab Notes:
  drawing of 189 lines, arcs and shapes, not listed
  text "DESIGN INFORMATION" at 314.503,161.447 h1.52
  text "MIN. TRACK WIDTH:" at 298.131,158.091 h1.52
  text "6" at 325.976,158.091 h1.52
  text "MIL" at 329.907,158.091 h1.52
  text "6" at 326,155 h1.52
  text "MIN. CLEARANCE:" at 298.131,154.938 h1.52
  text "MIL" at 329.907,154.938 h1.52
  text "19.685" at 320.836,151.836 h1.52
  text "MIN. VIA PAD SIZE:" at 298.131,151.785 h1.52
  text "MIL" at 329.907,151.785 h1.52
  text "0.05mm (2MIL)" at 315.784,148.486 h1.52
  text "MINIMUM ANNULAR RING" at 289.769,148.277 h1.52
  text "EXTERNAL" at 333.768,148.277 h1.52
  text "PER" at 294.849,145.48 h1.52
  text "IPC-D-275 CLASS 2 LEVEL C" at 300.437,145.48 h1.52
  text "MIL, HOLES" at 338.238,142.928 h1.52
  text "+/-" at 328.27,142.709 h1.52
  text "+/-" at 349.961,142.709 h1.52
  text "REGISTRATION TOLERANCES:" at 289.769,142.682 h1.52
  text "METAL" at 320.243,142.682 h1.52
  text "5" at 334.879,142.683 h1.52
  text "3" at 356.037,142.683 h1.52
  text "MIL" at 358.99,142.682 h1.52
  text "HOLE SIZE TOLERANCE (UNLESS OTHERWISE SPECIFIED):" at 289.769,140.185 h1.52
  text "+/-" at 349.961,140.112 h1.52
  text "3" at 356.037,140.085 h1.52
  text "MIL" at 358.99,140.085 h1.52
  text "MATERIAL:" at 287.87,136.589 h1.52
  text "FR-4 High Tg" at 312.926,133.324 h1.52
  text "X" at 309.257,133.122 h1.52
  text "FR-4" at 298.563,133.007 h1.52
  text "OTHER" at 336.358,133.007 h1.52
  text "62 MIL (1.6mm) +/-10%" at 306.694,129.374 h1.52
  text "X" at 303.643,129.312 h1.52
  text "THICKNESS:" at 289.769,129.165 h1.52
  text "OTHER" at 339.33,129.165 h1.52
  text "TOLERANCE:" at 289.769,125.652 h1.52
  text "X" at 311.314,125.652 h1.52
  text "ANSI IPC-6012 TYPE 3 CLASS 2" at 315.836,125.652 h1.52
  text "OTHER +/-" at 315.835,121.989 h1.52
  text "BOW & TWIST:" at 289.769,118.302 h1.52
  text "X" at 311.314,118.302 h1.52
  text "ANSI IPC-6012 TYPE 3 CLASS 2" at 315.836,118.302 h1.52
  text "OTHER +/-" at 315.835,114.576 h1.52
  text "DRILLING:" at 287.87,111.258 h1.52
  text "NC_DRILL FILES" at 332.599,108.586 h1.52
  text "REFERENCE:" at 289.769,108.486 h1.52
  text "X" at 306.463,108.484 h1.52
  text "AS SHOWN" at 310.984,108.486 h1.52
  text "X" at 329.348,108.486 h1.52
  text "OTHER" at 340.168,104.873 h1.52
  text "PTH COPPER THICKNESS:" at 289.761,104.783 h1.52
  text "X" at 318.697,104.783 h1.52
  text "20-30 um" at 321.948,104.783 h1.52
  text "BOARD FINISH:" at 287.87,101.034 h1.52
  text "SILKSCREEN:" at 291.812,98.237 h1.52
  text "X" at 316.14,98.237 h1.52
  text "TOP" at 319.112,98.237 h1.52
  text "BOTTOM" at 332.091,98.237 h1.52
  text "SILKSCREEN COLOR:" at 291.812,94.295 h1.52
  text "X" at 316.115,94.295 h1.52
  text "WHITE" at 319.112,94.295 h1.52
  text "OTHER" at 332.091,94.295 h1.52
  text "X" at 319.442,90.652 h1.52
  text "GREEN" at 322.439,90.652 h1.52
  text "OTHER" at 338.136,90.652 h1.52
  text "SOLDER RESIST COLOR:" at 291.812,90.477 h1.52
  text "MATTE" at 322.439,86.734 h1.52
  text "SEMI-GLOSS" at 338.125,86.717 h1.52
  text "IMMERSION GOLD (ENIG)" at 314.819,82.345 h1.52
  text "ENEPIG" at 348.793,82.162 h1.52
  text "SURFACE FINISH:" at 287.87,82.136 h1.52
  text "X" at 310.298,82.136 h1.52
  text "IMM. TIN/SILVER OR EQUIV" at 296.24,78.649 h1.52
  text "OTHER" at 332.599,78.549 h1.52
  text "ARRAY/PANEL:" at 287.87,74.602 h1.52
  text "CUT AND TRIM PER M1 BOARD OUTLINE" at 314.819,74.393 h1.52
  text "N.C. ROUTE" at 314.819,70.94 h1.52
  text "X" at 332.295,70.94 h1.52
  text "V. SCORE" at 336.816,70.94 h1.52
  text "CERTIFICATION:" at 287.87,67.66 h1.52
  text "MATERIALS AND WORKMANSHIP FOR ALL PCBS" at 306.285,67.66 h1.52
  text "TO MEET OR EXCEED THE REQUIREMENTS OF:" at 306.285,65.271 h1.52
  text "X" at 297.078,62.003 h1.52
  text "ANSI IPC-A-600F CLASS ->" at 300.329,62.003 h1.52
  text "X" at 342.188,62.003 h1.52
  text "2" at 344.982,62.003 h1.52
  text "1" at 336.981,61.965 h1.52
  text "3" at 353.973,61.965 h1.52
  text "X" at 317.702,58.252 h1.52
  text "RoHS" at 320.953,58.252 h1.52
  text "OTHER" at 337.321,58.252 h1.52
  text "PER ORDER" at 347.407,58.252 h1.52
  text "ALL BOARDS MUST MEET OR EXCEED UL94-V0 REQUIREMENTS." at 288.569,54.345 h1.52
  text "PCB MUST BEAR THE UL94V-0 UL REGISTERED MATERIAL ID NUMBER" at 288.569,51.397 h1.52
  text "ADDITIONAL REQUIREMENTS:" at 287.87,47.094 h1.52
  text "MICROSECTION:" at 289.769,44.373 h1.52
  text "YES" at 312.775,44.373 h1.52
  text "REQUIRED" at 334.657,40.707 h1.52
  text "BARE BOARD ELEC. TEST:" at 289.769,40.634 h1.52
  text "NONE" at 322.935,40.634 h1.52
  text "X" at 331.66,40.634 h1.52
  text "PER ORDER" at 349.693,40.634 h1.52
  text "X" at 291.202,36.752 h1.52
  text "VIAS REQUIRE NON-CONDUCTIVE FILL AND PLANARIZE" at 290.75,35.25 h1.5
  text "XX MIL VIAS REQUIRE CONDUCTIVE FILL AND PLANARIZE" at 294.243,32.787 h1.52
  text "OUTER XX MIL TRACES REQUIRE 50 OHM SINGLE-ENDED IMPEDANCE" at 294.218,28.637 h1.47
  text "LAYER 2 & 3 (INNER LAYERS) XX MIL WIDE, XX MIL SPACE / TRACES REQUIRE 100 OHM DIFFERENTIAL IMPEDANCE" at 294.015,22.65 h1.52
  text "X" at 25.992,11.502 h1.52
  text "X" at 27.365,7.097 h1.52
  text ".Layer_Name" at 14.656,-21.806 h1.52
M11 Gerber Information:
  lines w0.254: -7.417,-23.626 160.223,-23.626 ; -7.417,-18.462 160.274,-18.462 ; -7.417,-13.297 -7.417,-28.791 94.31,-28.791 160.274,-28.791 160.274,-13.297 -7.404,-13.297 -7.404,-28.791 32.614,-28.791 ; 55.194,-28.791 55.194,-13.297 ; 87.376,-18.462 87.376,-13.297 ; 108.712,-18.462 108.712,-13.297 ; 124.511,-28.956 124.511,-23.804
  text "ALL ARTWORK VIEWED FROM TOP SIDE" at -5.804,-16.654 h1.52
  text "BOARD #:" at 57.099,-16.654 h1.52
  text ".PRJ_Number" at 70.955,-16.654 h1.52
  text "REV:" at 92.405,-16.654 h1.52
  text ".PCB_Rev" at 99.809,-16.654 h1.52
  text "SVN REV:" at 113.69,-16.654 h1.52
  text ".VersionControl_RevNumber" at 126.543,-16.654 h1.52
  text "LAYER NAME =" at -5.804,-21.806 h1.52
  text "TID #:" at 57.099,-21.819 h1.52
  text ".TID" at 70.955,-21.819 h1.52
  text "PLOT NAME =" at -5.804,-27.034 h1.52
  text ".plot_File_Name" at 14.656,-27.034 h1.52
  text "GENERATED    :" at 57.15,-27.034 h1.52
  text ".Print_Date" at 79.235,-27.034 h1.52
  text ".Print_Time" at 97.752,-27.034 h1.52
  text "TEXAS INSTRUMENTS" at 129.87,-27.034 h1.52
M12 Stackup:
  drawing of 373 lines, arcs and shapes, not listed
  text "Layer" at 172.608,199.512 h1.52
  text "Name" at 183.02,199.512 h1.52
  text "Material" at 206.89,199.512 h1.52
  text "Thickness" at 228.728,199.512 h1.52
  text "Constant" at 245.234,199.512 h1.52
  text "Board Layer Stack" at 259.708,199.512 h1.52
  text "Top Overlay" at 183.02,196.464 h1.52
  text "Top Solder" at 183.02,193.416 h1.52
  text "Solder Resist" at 206.89,193.416 h1.52
  text "0.50mil" at 228.728,193.416 h1.52
  text "3.5" at 245.234,193.416 h1.52
  text "1" at 172.608,190.368 h1.52
  text "Top Layer" at 183.02,190.368 h1.52
  text "2.80mil" at 228.728,190.368 h1.52
  text "Dielectric 1" at 183.02,187.32 h1.52
  text "FR-4 High Tg" at 206.89,187.32 h1.52
  text "7.00mil" at 228.728,187.32 h1.52
  text "4.2" at 245.234,187.32 h1.52
  text "2" at 172.608,184.272 h1.52
  text "Signal Layer 1" at 183.02,184.272 h1.52
  text "1.40mil" at 228.728,184.272 h1.52
  text "Dielectric 2" at 183.02,181.224 h1.52
  text "FR-4 High Tg" at 206.89,181.224 h1.52
  text "14.00mil" at 228.728,181.224 h1.52
  text "4.2" at 245.234,181.224 h1.52
  text "3" at 172.608,178.176 h1.52
  text "Signal Layer 2" at 183.02,178.176 h1.52
  text "1.40mil" at 228.728,178.176 h1.52
  text "Dielectric 4" at 183.02,175.128 h1.52
  text "FR-4 High Tg" at 206.89,175.128 h1.52
  text "8.20mil" at 228.728,175.128 h1.52
  text "4.2" at 245.234,175.128 h1.52
  text "4" at 172.608,172.08 h1.52
  text "Signal Layer 3" at 183.02,172.08 h1.52
  text "1.40mil" at 228.728,172.08 h1.52
  text "Dielectric 5" at 183.02,169.032 h1.52
  text "FR-4 High Tg" at 206.89,169.032 h1.52
  text "14.00mil" at 228.728,169.032 h1.52
  text "4.2" at 245.234,169.032 h1.52
  text "5" at 172.608,165.984 h1.52
  text "Signal Layer 4" at 183.02,165.984 h1.52
  text "1.40mil" at 228.728,165.984 h1.52
  text "Dielectric 3" at 183.02,162.936 h1.52
  text "FR-4 High Tg" at 206.89,162.936 h1.52
  text "7.00mil" at 228.728,162.936 h1.52
  text "4.2" at 245.234,162.936 h1.52
  text "6" at 172.608,159.888 h1.52
  text "Bottom Layer" at 183.02,159.888 h1.52
  text "2.80mil" at 228.728,159.888 h1.52
  text "Bottom Solder" at 183.02,156.84 h1.52
  text "Solder Resist" at 206.89,156.84 h1.52
  text "0.50mil" at 228.728,156.84 h1.52
  text "3.5" at 245.234,156.84 h1.52
  text ".Layer_Name" at 14.656,-21.806 h1.52
M13 Component Bodies Top:
  text ".Layer_Name" at 14.656,-21.806 h1.52
M14 Component Bodies Bottom:
  text ".Layer_Name" at 14.656,-21.806 h1.52
M15 Courtyards Top:
  text ".Layer_Name" at 14.656,-21.806 h1.52
M16 Courtyards Bottom:
  text ".Layer_Name" at 14.656,-21.806 h1.52
Drill Drawing:
  circle w0.254: c171.798,77.258 r0.421
  circle w0.254: c171.798,77.258 r0.702
  circle w0.254: c171.798,64.627 r0.702
  lines w0.254: 171.097,57.61 171.798,57.96 172.5,57.61 172.149,58.311 172.5,59.013 171.798,58.662 171.097,59.013 171.448,58.311 171.097,57.61 ; 171.097,62.171 172.5,62.171 171.798,60.767 171.097,62.171 ; 171.097,67.083 172.5,67.083 172.5,68.486 171.097,68.486 171.097,67.083 ; 171.097,70.591 171.448,70.591 171.798,70.241 172.149,70.591 172.5,70.591 172.149,70.942 172.5,71.293 172.149,71.293 171.798,71.644 171.448,71.293 171.097,71.293 171.448,70.942 171.097,70.591 ; 171.097,73.398 171.097,73.749 171.448,74.1 171.097,74.451 171.097,74.802 171.448,74.802 171.798,74.451 172.149,74.802 172.5,74.802 172.5,74.451 172.149,74.1 172.5,73.749 172.5,73.398 172.149,73.398 171.798,73.749 171.448,73.398 171.097,73.398 ; 171.097,79.714 172.5,79.714 172.5,81.117 171.097,81.117 171.097,79.714 ; 171.097,84.275 172.5,84.275 171.798,82.871 171.097,84.275 ; 171.377,67.364 172.219,67.364 172.219,68.206 171.377,68.206 171.377,67.364 ; 171.377,83.994 172.219,83.994 171.798,83.152 171.377,83.994
  lines w0.305: 169.824,56.662 251.908,56.662 ; 169.824,85.082 251.908,85.082 ; 178.406,53.505 178.406,88.24 ; 186.843,53.505 186.843,88.24 ; 203.012,53.505 203.012,88.24 ; 209.594,53.505 209.594,88.24 ; 219.123,53.505 219.123,88.24 ; 237.521,53.505 237.521,88.24 ; 169.824,53.505 251.908,53.505 251.908,88.24 169.824,88.24 169.824,53.505
  text "Symbol" at 171.719,86.029 h1.83
  text "Quantity" at 179.353,86.029 h1.83
  text "Finished Hole Size" at 187.79,86.029 h1.83
  text "Plated" at 203.959,86.029 h1.83
  text "Hole Type" at 210.541,86.029 h1.83
  text "Drill Layer Pair" at 220.07,86.029 h1.83
  text "Hole Tolerance" at 238.468,86.029 h1.83
  text "12" at 179.353,82.871 h1.52
  text "7.87mil (0.200mm)" at 187.79,82.871 h1.52
  text "PTH" at 203.959,82.871 h1.52
  text "Round" at 210.541,82.871 h1.52
  text "Top Layer - Bottom Layer" at 220.07,82.871 h1.52
  text "2282" at 179.353,79.714 h1.52
  text "8.00mil (0.203mm)" at 187.79,79.714 h1.52
  text "PTH" at 203.959,79.714 h1.52
  text "Round" at 210.541,79.714 h1.52
  text "Top Layer - Bottom Layer" at 220.07,79.714 h1.52
  text "232" at 179.353,76.556 h1.52
  text "16.00mil (0.406mm)" at 187.79,76.556 h1.52
  text "PTH" at 203.959,76.556 h1.52
  text "Round" at 210.541,76.556 h1.52
  text "Top Layer - Bottom Layer" at 220.07,76.556 h1.52
  text "58" at 179.353,73.398 h1.52
  text "40.00mil (1.016mm)" at 187.79,73.398 h1.52
  text "PTH" at 203.959,73.398 h1.52
  text "Round" at 210.541,73.398 h1.52
  text "Top Layer - Bottom Layer" at 220.07,73.398 h1.52
  text "28" at 179.353,70.241 h1.52
  text "45.28mil (1.150mm)" at 187.79,70.241 h1.52
  text "PTH" at 203.959,70.241 h1.52
  text "Round" at 210.541,70.241 h1.52
  text "Top Layer - Bottom Layer" at 220.07,70.241 h1.52
  text "1" at 179.353,67.083 h1.52
  text "63.00mil (1.600mm)" at 187.79,67.083 h1.52
  text "PTH" at 203.959,67.083 h1.52
  text "Round" at 210.541,67.083 h1.52
  text "Top Layer - Bottom Layer" at 220.07,67.083 h1.52
  text "4" at 179.353,63.925 h1.52
  text "118.11mil (3.000mm)" at 187.79,63.925 h1.52
  text "PTH" at 203.959,63.925 h1.52
  text "Round" at 210.541,63.925 h1.52
  text "Top Layer - Bottom Layer" at 220.07,63.925 h1.52
  text "7" at 179.353,60.767 h1.52
  text "125.98mil (3.200mm)" at 187.79,60.767 h1.52
  text "PTH" at 203.959,60.767 h1.52
  text "Round" at 210.541,60.767 h1.52
  text "Top Layer - Bottom Layer" at 220.07,60.767 h1.52
  text "4" at 179.353,57.61 h1.52
  text "270.00mil (6.858mm)" at 187.79,57.61 h1.52
  text "PTH" at 203.959,57.61 h1.52
  text "Round" at 210.541,57.61 h1.52
  text "Top Layer - Bottom Layer" at 220.07,57.61 h1.52
  text "2628 Total" at 179.353,54.452 h1.52
  text ".Layer_Name" at 14.656,-21.806 h1.52
M17 Embedded Cavity:
  text ".Layer_Name" at 14.656,-21.806 h1.52
M18 Embedded Assembly:
  text ".Layer_Name" at 14.656,-21.806 h1.52
M19 Embedded Keepout:
  text ".Layer_Name" at 14.656,-21.806 h1.52

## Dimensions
0,0 to 154.94,0 on M2 Board Dimensions
0,-10.16 to 25.4,-10.16 on M2 Board Dimensions
0,0 to 0,104.14 on M2 Board Dimensions
0,0 to 154.94,0 on M2 Board Dimensions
